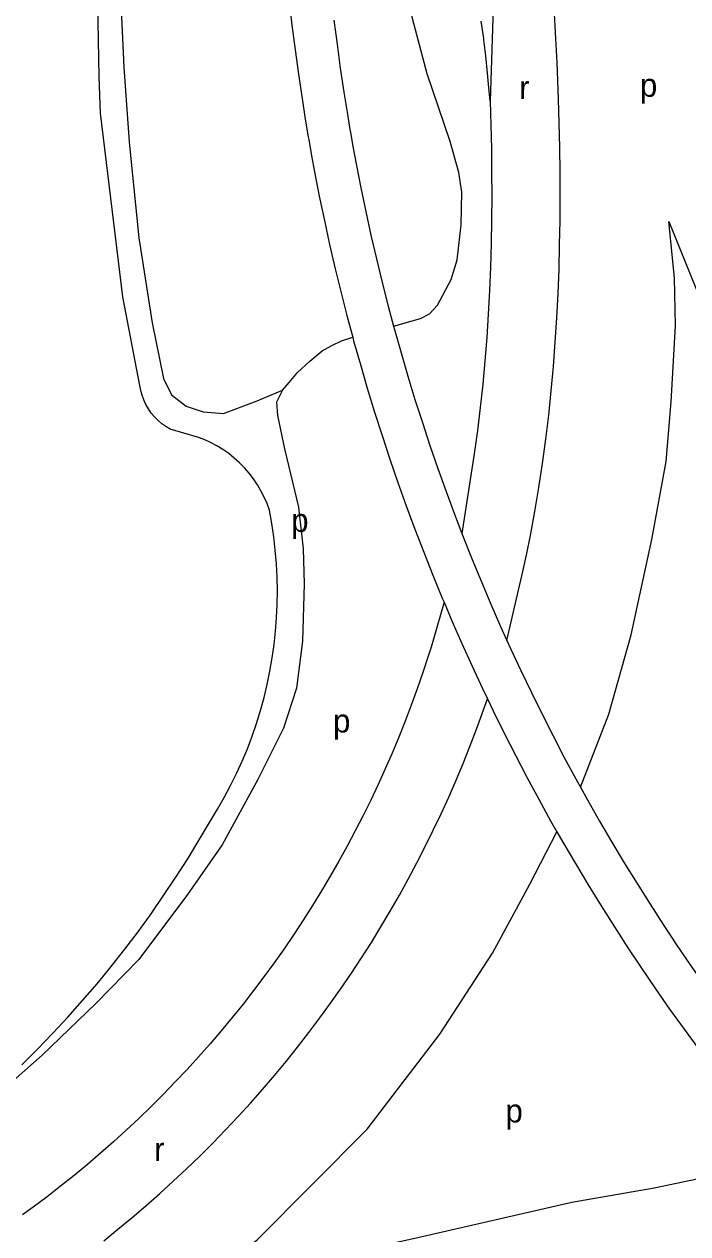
# Model space of a CAD drawing. Extents: x 157646 to 159241, y 379213 to 381217.
# Drawn here: x 157924.6 to 158038.3, y 379568.3 to 379775.7 of the extents above; entities that cross this region are included whole.
import ezdxf

# ---------------------------------------------------------------- set-up
doc = ezdxf.new("R2010")
doc.units = 0
for name, color, linetype in [('BLT_Basislijn', 7, 'Continuous'), ('BLT_Centroide', 7, 'Continuous'), ('BLT_Gemeentegrens', 7, 'Continuous'), ('BLT_Vlakafsluiter', 7, 'Continuous')]:
    doc.layers.add(name, color=color, linetype=linetype)

msp = doc.modelspace()

# ---------------------------------------------------------------- linework, layer by layer
at = {"layer": 'BLT_Basislijn'}
for points in [[(157987.87, 379723.86), (157992.47, 379725.18), (157994, 379725.99), (157995.41, 379727.48), (157997.75, 379731.88), (157998.78, 379735.25), (157999.44, 379741.25), (157999.55, 379746.88), (157999.06, 379750.25), (157997.57, 379755.55), (157993.62, 379767.16), (157991.09, 379776.62), (157989.31, 379784.96), (157987.25, 379793.49), (157986.03, 379800.79), (157985.17, 379808.59), (157984.14, 379818.99), (157983.85, 379824.23)], [(157967.12, 379816.79), (157967.28, 379813.32), (157967.63, 379807.02), (157968.05, 379800.71), (157968.53, 379794.4), (157969.09, 379788.09), (157969.5, 379783.89), (157969.96, 379779.68), (157970.45, 379775.48), (157970.98, 379771.28), (157971.56, 379767.08), (157972.18, 379762.89), (157972.74, 379759.38), (157973.25, 379756.36), (157973.33, 379755.87), (157973.82, 379753.1), (157974.33, 379750.34), (157975.14, 379746.17), (157976, 379742.02), (157976.91, 379737.87), (157977.87, 379733.73), (157978.87, 379729.61), (157979.92, 379725.49), (157980.87, 379721.98)], [(157941.26, 379794.25), (157940.84, 379785.65), (157941.66, 379768.27), (157942.56, 379755.44), (157944.2, 379739.05), (157946.5, 379724.46), (157948.42, 379714.93), (157949.82, 379712.12), (157952.35, 379710.15), (157955.25, 379709.22), (157958.72, 379708.94), (157964.51, 379711.11), (157968.81, 379712.89)], [(158007.28, 379669.99), (158010.02, 379681.84), (158010.68, 379684.91), (158011.3, 379687.98), (158012.07, 379692.09), (158012.76, 379696.21), (158013.39, 379700.35), (158013.95, 379704.49), (158014.44, 379708.64), (158014.88, 379712.79), (158015.25, 379716.95), (158015.57, 379721.12), (158015.83, 379725.29), (158016.04, 379729.46), (158016.2, 379733.63), (158016.31, 379737.81), (158016.38, 379741.98), (158016.4, 379746.16), (158016.38, 379750.33), (158016.33, 379754.5), (158016.24, 379758.68), (158016.11, 379762.85), (158015.86, 379769.1), (158015.62, 379774.22), (158015.56, 379775.35), (158015.19, 379781.6)], [(157977.65, 379776.36), (157978.17, 379772.23), (157978.74, 379768.11), (157979.35, 379763.99), (157979.9, 379760.55), (157980.39, 379757.58), (157980.47, 379757.11), (157980.95, 379754.39), (157981.45, 379751.69), (157982.25, 379747.6), (157983.09, 379743.53), (157983.98, 379739.46), (157984.92, 379735.41), (157985.91, 379731.36), (157986.94, 379727.33), (157987.87, 379723.86)], [(158004.42, 379762.45), (158004.17, 379764.74), (158003.96, 379767.23), (158003.65, 379770.22), (158003.33, 379772.96), (158003.3, 379773.2), (158002.89, 379776.17)], [(158004.42, 379762.45), (158004.53, 379758.37), (158004.61, 379754.29), (158004.66, 379750.23), (158004.67, 379746.16), (158004.64, 379742.11), (158004.56, 379738.06), (158004.45, 379734.01), (158004.28, 379729.98), (158004.07, 379725.95), (158003.81, 379721.94), (158003.5, 379717.93), (158003.13, 379713.93), (158002.7, 379709.95), (158002.22, 379705.98), (158001.68, 379702.02), (157999.57, 379688.32)], [(158019.89, 379644.84), (158024.72, 379657.39), (158028.56, 379670.97), (158032.11, 379687.31), (158034.55, 379700.71), (158035.39, 379710.92), (158036.16, 379723.92), (158035.98, 379732.16), (158035.04, 379741.81)], [(158035.04, 379741.81), (158040.59, 379727.99), (158047.3, 379715.86), (158053.2, 379706.18), (158067.13, 379686.02), (158077.95, 379670.94), (158085.82, 379660.94), (158090.4, 379656.02), (158094.31, 379668.8), (158095.01, 379673.51)], [(157987.87, 379723.86), (157988.01, 379723.31), (157989.14, 379719.3), (157990.31, 379715.31), (157991.53, 379711.33), (157992.79, 379707.37), (157994.1, 379703.42), (157995.45, 379699.48), (157996.85, 379695.56), (157998.29, 379691.66), (157999.57, 379688.32)], [(157968.81, 379712.89), (157969.97, 379714.21), (157971.4, 379715.92), (157973.51, 379717.91), (157975.62, 379719.68), (157977.27, 379720.6), (157978.96, 379721.39), (157980.87, 379721.98)], [(157980.87, 379721.98), (157981.02, 379721.39), (157982.17, 379717.31), (157983.36, 379713.23), (157984.6, 379709.17), (157985.89, 379705.13), (157987.23, 379701.1), (157988.61, 379697.08), (157990.04, 379693.08), (157991.51, 379689.1), (157993.03, 379685.14), (157994.6, 379681.19), (157996.21, 379677.27), (157996.51, 379676.55)], [(157968.81, 379712.89), (157967.78, 379710.83), (157967.97, 379708.58), (157969.19, 379702.86), (157971.6, 379692.84), (157972.35, 379685.72), (157972.54, 379679.73), (157972.25, 379669.89), (157971.22, 379661.84), (157968.98, 379655), (157964.6, 379646.15), (157958.48, 379634.98), (157952.58, 379626.45), (157944.22, 379615.31), (157936.85, 379607.77), (157927.67, 379598.91), (157912.26, 379585.31), (157903.94, 379577.97), (157899.23, 379574.71), (157896.89, 379573.19)], [(157999.57, 379688.32), (158001.32, 379683.91), (158002.9, 379680.06), (158004.52, 379676.22), (158006.19, 379672.41), (158007.28, 379669.99)], [(157996.51, 379676.55), (157995.29, 379672.23), (157994.45, 379669.43), (157994.34, 379669.1), (157994.33, 379669.05), (157993.78, 379667.3), (157992.86, 379664.49), (157991.9, 379661.7), (157990.89, 379658.93), (157989.84, 379656.17), (157988.75, 379653.43), (157987.61, 379650.7), (157986.43, 379648), (157985.21, 379645.31), (157983.95, 379642.64), (157982.64, 379640), (157981.3, 379637.37), (157979.91, 379634.76), (157978.49, 379632.18), (157977.02, 379629.62), (157975.51, 379627.08), (157973.97, 379624.56), (157972.38, 379622.07), (157970.76, 379619.61), (157969.1, 379617.17), (157967.4, 379614.76), (157965.66, 379612.37), (157963.89, 379610.01), (157962.07, 379607.68), (157960.23, 379605.38), (157958.34, 379603.11), (157956.43, 379600.86), (157954.47, 379598.65), (157952.49, 379596.47), (157950.46, 379594.32), (157948.41, 379592.2), (157946.32, 379590.11), (157944.2, 379588.06), (157942.05, 379586.04), (157939.87, 379584.05), (157937.65, 379582.1), (157935.41, 379580.18), (157933.14, 379578.3), (157930.83, 379576.46), (157928.5, 379574.65), (157926.14, 379572.87), (157924.31, 379571.54)], [(157996.51, 379676.55), (157997.86, 379673.36), (157999.56, 379669.47), (158001.31, 379665.6), (158003.1, 379661.75), (158003.94, 379660)], [(158007.28, 379669.99), (158007.9, 379668.62), (158009.66, 379664.85), (158011.46, 379661.09), (158013.3, 379657.36), (158015.18, 379653.65), (158017.11, 379649.96), (158019.08, 379646.3), (158019.89, 379644.84)], [(157938.2, 379567.11), (157940.65, 379569.08), (157943.07, 379571.08), (157945.45, 379573.11), (157947.81, 379575.19), (157950.13, 379577.3), (157952.41, 379579.45), (157954.67, 379581.63), (157956.89, 379583.85), (157959.07, 379586.1), (157961.22, 379588.39), (157963.33, 379590.71), (157965.41, 379593.06), (157967.45, 379595.44), (157969.45, 379597.86), (157971.41, 379600.31), (157973.34, 379602.78), (157975.23, 379605.29), (157977.07, 379607.83), (157978.88, 379610.39), (157980.65, 379612.99), (157982.37, 379615.61), (157984.06, 379618.25), (157985.7, 379620.92), (157987.3, 379623.62), (157988.86, 379626.35), (157990.38, 379629.09), (157991.85, 379631.86), (157993.28, 379634.66), (157994.67, 379637.47), (157996.01, 379640.31), (157997.3, 379643.16), (157998.56, 379646.04), (157999.76, 379648.94), (158000.93, 379651.85), (158002.04, 379654.78), (158003.94, 379660)], [(158003.94, 379660), (158004.94, 379657.92), (158006.82, 379654.11), (158008.74, 379650.33), (158010.71, 379646.57), (158012.72, 379642.83), (158014.77, 379639.11), (158015.84, 379637.23)], [(158019.89, 379644.84), (158021.1, 379642.66), (158023.15, 379639.04), (158025.25, 379635.44), (158027.39, 379631.87), (158029.57, 379628.33), (158031.79, 379624.81), (158034.05, 379621.32), (158036.35, 379617.85), (158038.69, 379614.41), (158041.07, 379611), (158043.49, 379607.61), (158045.95, 379604.25), (158048.45, 379600.93), (158050.99, 379597.63), (158053.56, 379594.36), (158056.18, 379591.12), (158058.82, 379587.91), (158061.51, 379584.73), (158064.23, 379581.58), (158064.51, 379581.28)], [(157952.68, 379557.57), (157964.48, 379567.25), (157983.33, 379586.26), (157995.78, 379602.49), (158004.79, 379616.42), (158011.18, 379628.23), (158015.84, 379637.23)], [(158015.84, 379637.23), (158016.87, 379635.42), (158019.01, 379631.75), (158021.19, 379628.11), (158023.41, 379624.5), (158025.68, 379620.91), (158027.99, 379617.34), (158030.33, 379613.81), (158032.72, 379610.3), (158035.15, 379606.81), (158037.62, 379603.36), (158040.13, 379599.94), (158042.68, 379596.54), (158045.27, 379593.17), (158047.89, 379589.84), (158050.56, 379586.53), (158053.26, 379583.26), (158055.84, 379580.21)], [(157952.68, 379557.57), (157962.57, 379560.91), (157974.09, 379563.72), (157991.5, 379567.56), (158018.38, 379573.72), (158032.52, 379576.16), (158045.07, 379578.78), (158055.84, 379580.21)]]:
    msp.add_lwpolyline(points, dxfattribs=at)
at = {"layer": 'BLT_Gemeentegrens'}
msp.add_lwpolyline([(157924.2, 379597.26), (157926.88, 379599.94), (157929.51, 379602.67), (157932.08, 379605.45), (157934.6, 379608.28), (157937.06, 379611.16), (157939.46, 379614.09), (157941.8, 379617.06), (157944.09, 379620.08), (157946.31, 379623.15), (157948.47, 379626.26), (157950.57, 379629.41), (157952.61, 379632.6), (157954.58, 379635.84), (157956.49, 379639.11), (157957.7, 379641.08), (157958.86, 379643.08), (157959.94, 379645.12), (157960.96, 379647.2), (157961.92, 379649.3), (157962.81, 379651.44), (157963.63, 379653.6), (157964.38, 379655.79), (157965.06, 379658), (157965.67, 379660.23), (157966.21, 379662.48), (157966.67, 379664.74), (157967.07, 379667.02), (157967.39, 379669.31), (157967.64, 379671.61), (157967.82, 379673.91), (157967.92, 379676.22), (157967.95, 379678.54), (157967.9, 379680.85), (157967.79, 379683.16), (157967.59, 379685.46), (157967.33, 379687.76), (157966.99, 379690.05), (157966.59, 379692.32), (157966.18, 379693.46), (157965.7, 379694.58), (157965.15, 379695.66), (157964.54, 379696.71), (157963.86, 379697.72), (157963.12, 379698.68), (157962.32, 379699.6), (157961.48, 379700.47), (157960.57, 379701.28), (157959.62, 379702.03), (157958.63, 379702.73), (157957.59, 379703.36), (157956.52, 379703.93), (157955.41, 379704.43), (157954.28, 379704.86), (157949.6, 379706.23), (157948.86, 379706.67), (157948.16, 379707.17), (157947.51, 379707.73), (157946.91, 379708.34), (157946.36, 379709), (157945.87, 379709.71), (157945.44, 379710.45), (157945.07, 379711.23), (157944.78, 379712.04), (157944.55, 379712.87), (157944.4, 379713.72), (157941.47, 379728.91), (157937.65, 379760.38), (157937.43, 379766.64), (157937.29, 379772.89), (157937.22, 379779.15)], dxfattribs=at)
at = {"layer": 'BLT_Vlakafsluiter'}
msp.add_line((158005.7, 379801.99), (158004.42, 379762.45), dxfattribs=at)

# ---------------------------------------------------------------- texts
at = {"layer": 'BLT_Centroide'}
for s, p in [('r', (158009.39, 379762.81)), ('p', (158030.06, 379763.21)), ('p', (157970.32, 379688.61)), ('p', (157977.49, 379654.23)), ('p', (158007.02, 379587.38)), ('r', (157946.85, 379580.8))]:
    msp.add_text(s, height=4, dxfattribs=at).set_placement(p)

doc.saveas('drawing.dxf')
